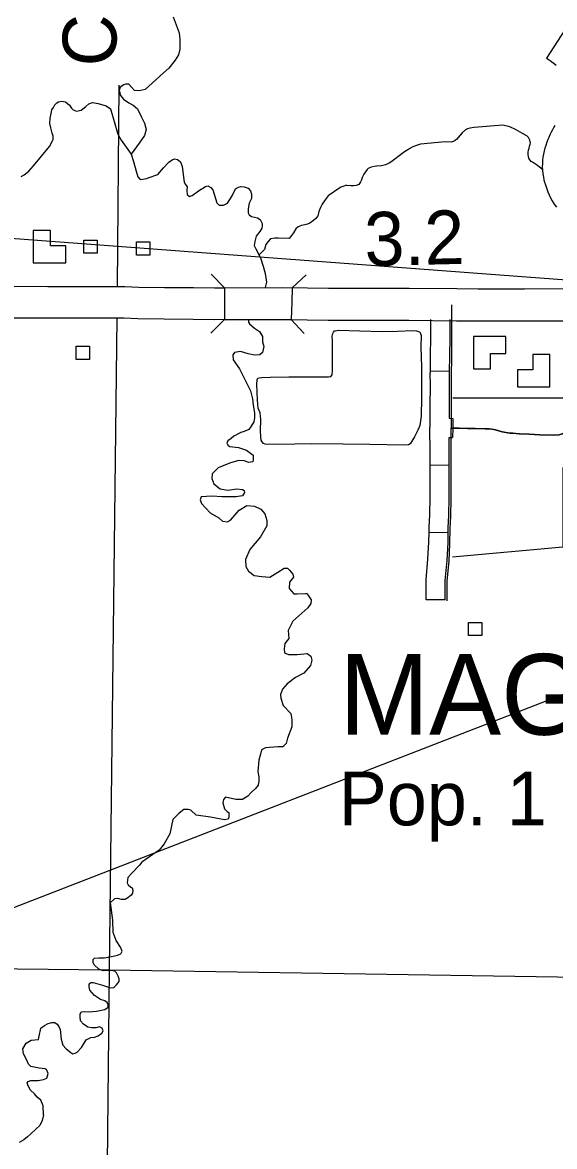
# Model space of a CAD drawing. Extents: x 61396 to 64680, y 55472 to 57605.
# Drawn here: x 62426.4 to 62557, y 55839.3 to 56115 of the extents above; entities that cross this region are included whole.
import ezdxf

# ---------------------------------------------------------------- set-up
doc = ezdxf.new("R2010")
doc.units = 0
for name, color, linetype in [('15', 7, 'Continuous'), ('22', 7, 'Continuous'), ('32', 7, 'Continuous'), ('34', 7, 'Continuous'), ('35', 7, 'Continuous'), ('37', 7, 'Continuous'), ('48', 7, 'Continuous'), ('5', 7, 'Continuous'), ('56', 7, 'Continuous'), ('58', 7, 'Continuous'), ('6', 7, 'Continuous'), ('Default', 7, 'Continuous')]:
    doc.layers.add(name, color=color, linetype=linetype)

msp = doc.modelspace()

# ---------------------------------------------------------------- linework, layer by layer
at = {"layer": '15'}
for points in [[(62424.38, 56050.34), (62432.67, 56050.29), (62439.78, 56050.29), (62447.11, 56050.29), (62451.57, 56050.29), (62454.96, 56050.13), (62461.25, 56050.03), (62468.36, 56049.98), (62473.53, 56049.93), (62476, 56049.94), (62475.99, 56046.21), (62475.98, 56042.13)], [(62476, 56049.94), (62490.28, 56049.98), (62492.59, 56049.94)], [(62492.59, 56049.94), (62492.49, 56046.4), (62492.37, 56042.13), (62496.24, 56042.07), (62501.46, 56041.97), (62512.44, 56041.97), (62518.65, 56041.97), (62521.23, 56041.97), (62532.91, 56041.87), (62538.17, 56041.81), (62549.6, 56041.81), (62559.28, 56041.87)], [(62559.33, 56049.68), (62549.58, 56049.63), (62538.21, 56049.63), (62532.98, 56049.68), (62521.26, 56049.78), (62518.65, 56049.78), (62512.44, 56049.78), (62501.54, 56049.78), (62496.38, 56049.88), (62492.59, 56049.94)], [(62475.98, 56042.13), (62473.5, 56042.12), (62468.29, 56042.17), (62461.16, 56042.22), (62454.72, 56042.32), (62451.4, 56042.48), (62447.11, 56042.48), (62439.78, 56042.48), (62432.65, 56042.48), (62424.35, 56042.53)], [(62475.98, 56042.13), (62490.23, 56042.17), (62492.37, 56042.13)]]:
    msp.add_lwpolyline(points, dxfattribs=at)
at = {"layer": '22'}
for points in [[(62560.42, 56114.61), (62555.01, 56106.25), (62555.4, 56106.02), (62555.86, 56105.72), (62556.3, 56105.41), (62556.88, 56104.95), (62557.34, 56104.55)], [(62557.02, 56089.74), (62556.71, 56089.21), (62556.44, 56088.72), (62556.14, 56088.14), (62555.81, 56087.46), (62555.52, 56086.79), (62555.31, 56086.29), (62555.07, 56085.66), (62554.81, 56084.88), (62554.6, 56084.23), (62554.41, 56083.52), (62554.22, 56082.7), (62554.1, 56081.97), (62554.02, 56081.21), (62553.97, 56080.37), (62553.96, 56079.59), (62554, 56078.83), (62554.09, 56077.93), (62554.23, 56077.08), (62554.37, 56076.44), (62554.52, 56075.87), (62554.7, 56075.23), (62554.95, 56074.44), (62555.31, 56073.48), (62555.62, 56072.77), (62555.97, 56072.04), (62556.37, 56071.32), (62556.87, 56070.5), (62557.4, 56069.75)]]:
    msp.add_lwpolyline(points, dxfattribs=at)
at = {"layer": '32'}
for p, q in [((62526.41, 56029.6), (62531.1, 56029.51)), ((62531.11, 56006.39), (62526.42, 56006.35)), ((62530.87, 55989.84), (62526.18, 55989.91)), ((62530.15, 55973.4), (62525.46, 55973.4))]:
    msp.add_line(p, q, dxfattribs=at)
for points in [[(62531.64, 56045.78), (62531.71, 56042.56), (62531.71, 56040.2), (62531.71, 56037.67), (62531.65, 56032.89), (62531.56, 56028.4), (62531.59, 56026.04), (62531.56, 56020.42), (62531.56, 56016.05), (62531.56, 56015.52)], [(62526.54, 56042.17), (62526.54, 56040.48), (62526.54, 56037.95), (62526.48, 56033.2), (62526.41, 56029.6)], [(62531.23, 56042.13), (62531.23, 56040.48), (62531.23, 56037.93), (62531.17, 56033.12), (62531.1, 56029.51)], [(62526.41, 56029.6), (62526.39, 56028.68), (62526.42, 56026.3), (62526.39, 56020.69), (62526.39, 56016.31), (62526.4, 56015.78)], [(62531.1, 56029.51), (62531.08, 56028.66), (62531.11, 56026.32), (62531.08, 56020.68), (62531.08, 56017.94)], [(62531.08, 56017.94), (62531.97, 56017.9), (62531.97, 56015.51), (62531.96, 56013.21)], [(62526.42, 56006.35), (62526.42, 56006.58), (62526.42, 56009.32), (62526.4, 56015.78)], [(62530.63, 55973.13), (62530.63, 55977.95), (62531.07, 55982.95), (62531.31, 55987.16), (62531.37, 55990.93), (62531.5, 55993.83), (62531.62, 55998.34), (62531.62, 56002.11), (62531.59, 56006.31), (62531.59, 56009.05), (62531.56, 56015.52)], [(62531.56, 56015.52), (62533.52, 56015.49), (62535.58, 56015.4), (62537.5, 56015.43), (62539.96, 56015.34), (62540.92, 56015.31), (62541.59, 56015.28), (62542.46, 56015.08), (62544.09, 56014.62), (62545.97, 56014.27), (62546.76, 56014.24), (62548.32, 56014.15), (62550.76, 56014.04), (62552.01, 56013.92), (62553.37, 56013.83), (62556.77, 56013.75), (62558.13, 56013.86), (62558.8, 56014.09), (62559.55, 56014.61)], [(62531.11, 56006.39), (62531.11, 56006.59), (62531.11, 56009.33), (62531.09, 56013.24)], [(62531.09, 56013.24), (62531.96, 56013.21)], [(62526.18, 55989.91), (62526.21, 55991.27), (62526.33, 55994.18), (62526.45, 55998.64), (62526.45, 56002.37), (62526.42, 56006.35)], [(62530.87, 55989.84), (62530.89, 55991.13), (62531.02, 55994.02), (62531.14, 55998.58), (62531.14, 56002.39), (62531.11, 56006.39)], [(62525.46, 55973.4), (62525.46, 55978.32), (62525.9, 55983.4), (62526.15, 55987.52), (62526.18, 55989.91)], [(62530.15, 55973.4), (62530.15, 55978.12), (62530.58, 55983.06), (62530.83, 55987.34), (62530.87, 55989.84)]]:
    msp.add_lwpolyline(points, dxfattribs=at)
at = {"layer": '34'}
msp.add_lwpolyline([(62561.74, 56014.61), (62558.8, 56014.09), (62558.13, 56013.86), (62556.77, 56013.75), (62553.37, 56013.83), (62552.01, 56013.92), (62550.76, 56014.04), (62548.32, 56014.15), (62546.76, 56014.24), (62545.97, 56014.27), (62544.09, 56014.62), (62542.46, 56015.08), (62541.59, 56015.28), (62540.92, 56015.31), (62539.96, 56015.34), (62537.5, 56015.43), (62535.58, 56015.4), (62533.52, 56015.49), (62531.97, 56015.51)], dxfattribs=at)
at = {"layer": '35'}
for points in [[(62463.37, 56116.42), (62464.12, 56114.43), (62464.87, 56112.54), (62465.01, 56110.88), (62465.02, 56108.53), (62464.69, 56107.11), (62463.92, 56105.79), (62462.32, 56103.8), (62460.94, 56102.62), (62456.54, 56098.59), (62455.04, 56098.29), (62453.89, 56098.39), (62453.18, 56099.14), (62452.48, 56099.9), (62451.73, 56099.9), (62451.28, 56099.75), (62450.43, 56099.19), (62450.18, 56098.34), (62450.48, 56097.09), (62451.18, 56096.19), (62452.48, 56095.34), (62453.58, 56094.78), (62454.64, 56093.83), (62455.64, 56091.83), (62456.39, 56090.37), (62456.79, 56088.77), (62456.34, 56087.32), (62455.09, 56085.41), (62453.08, 56082.7)], [(62426.11, 56077.28), (62426.82, 56077.62), (62428.01, 56078.54), (62429.1, 56079.83), (62433.09, 56084.6), (62433.8, 56086), (62433.98, 56086.29), (62433.98, 56087.14), (62433.74, 56087.92), (62433.35, 56089.19), (62433.17, 56090.22), (62433.25, 56091.54), (62433.47, 56092.68), (62433.63, 56093.59), (62434.02, 56094.2), (62434.4, 56094.81), (62434.83, 56095.33), (62435.26, 56095.59), (62436, 56095.71), (62436.95, 56095.55), (62437.94, 56094.77), (62438.47, 56094.03), (62438.83, 56093.6), (62439.68, 56093.28), (62440.8, 56093.54), (62442, 56094.39), (62442.67, 56095.04), (62443.63, 56095.39), (62444.98, 56095.18), (62446.94, 56094.55), (62448, 56093.83), (62449.83, 56087.67), (62450.63, 56086.16), (62452.28, 56083.86), (62453.08, 56082.7), (62453.63, 56080.9), (62454.34, 56078.6), (62454.69, 56077.19), (62455.29, 56076.54), (62456.94, 56076.79), (62457.3, 56076.91)], [(62554.04, 56078.89), (62553.97, 56078.95), (62553.3, 56079.58), (62552.81, 56079.98), (62552.08, 56080.46), (62551.51, 56080.78), (62551.22, 56080.96), (62550.89, 56081.33), (62550.63, 56081.76), (62550.48, 56082.54), (62550.52, 56083.23), (62550.57, 56083.73), (62550.74, 56084.18), (62550.79, 56084.68), (62550.96, 56085.22), (62551.05, 56085.51), (62551.01, 56085.79), (62550.93, 56086.16), (62550.6, 56086.81), (62550.15, 56087.2), (62549.1, 56087.77), (62547.41, 56088.78), (62546.01, 56089.43), (62544.24, 56089.87), (62537.28, 56089.27), (62536.19, 56089.08), (62535.6, 56088.94), (62535.1, 56088.7), (62534.28, 56087.98), (62533.79, 56087.4), (62533.28, 56086.79), (62533.01, 56086.38), (62532.58, 56086.05), (62532.12, 56085.84), (62531.62, 56085.7), (62530.15, 56085.78), (62524.06, 56085.21), (62523.1, 56084.83), (62522.23, 56084.52), (62521.46, 56084.12), (62520.94, 56083.82), (62520.14, 56083.3), (62518.82, 56082.34), (62517.81, 56081.5), (62517.01, 56080.97), (62516.4, 56080.54), (62515.51, 56080.1), (62514.48, 56079.88), (62513.32, 56079.75), (62512.67, 56079.67), (62511.95, 56079.52), (62511.27, 56079.25), (62510.97, 56078.96), (62510.55, 56078.38)], [(62457.3, 56076.91), (62459.62, 56077.75), (62460.99, 56079.37), (62462.36, 56080.8), (62463.11, 56081.36), (62463.74, 56081.55), (62464.42, 56081.43), (62465.23, 56080.86), (62465.61, 56079.68), (62466.11, 56075.87), (62466.42, 56075.25), (62466.79, 56074.69), (62466.73, 56073.82), (62466.79, 56072.82), (62467.42, 56072.32), (62468.04, 56072.57), (62469.6, 56073.75), (62471.35, 56074.81), (62471.91, 56074.94), (62472.66, 56074.56), (62473.09, 56073.94), (62474.09, 56070.82), (62474.65, 56070.2), (62475.78, 56070.2), (62476.71, 56070.7), (62477.9, 56072.51), (62478.71, 56074.19), (62479.39, 56074.63), (62480.02, 56074.81), (62480.83, 56074.75), (62481.76, 56074.38), (62482.39, 56073.75), (62482.58, 56072.94), (62482.58, 56071.88), (62482.08, 56070.7), (62481.76, 56069.32), (62481.83, 56068.33), (62482.01, 56067.83), (62482.64, 56067.45), (62484.07, 56067.08), (62484.7, 56066.7), (62485.26, 56065.71), (62485.2, 56065.08), (62485.13, 56064.58), (62484.63, 56063.77), (62483.76, 56062.59), (62483.45, 56061.28), (62483.26, 56060.34), (62483.64, 56059.53), (62484.82, 56057.29), (62485.44, 56055.23), (62485.94, 56053.48), (62486.26, 56051.3), (62485.93, 56049.98)], [(62510.55, 56078.38), (62510.16, 56077.8), (62509.74, 56077.03), (62509.6, 56076.46), (62509.37, 56075.95), (62509.1, 56075.51), (62508.95, 56075.25), (62508.27, 56075.04), (62507.71, 56074.96), (62506.99, 56074.97), (62506.01, 56075.06), (62505.67, 56075.08), (62505.24, 56074.88), (62504.28, 56074.54), (62504.28, 56074.47), (62501.43, 56072.5), (62500.67, 56071.5), (62499.98, 56070.45), (62499.51, 56069.65), (62499.13, 56068.63), (62499.08, 56068.28), (62498.88, 56067.62), (62498.4, 56066.97), (62497.82, 56066.42), (62496.93, 56065.77), (62496.37, 56065.59), (62495.72, 56065.41), (62494.85, 56065.23), (62494.05, 56064.92), (62493.5, 56064.43), (62492.93, 56063.44), (62492.42, 56062.74), (62491.85, 56062.03), (62489.12, 56062.11), (62488.33, 56062.11), (62487.27, 56061.95), (62486.69, 56061.31), (62486.16, 56060.57), (62485.79, 56059.3), (62484.41, 56057.98)], [(62481.85, 56042.14), (62481.89, 56041.51), (62482.14, 56041.13), (62483.39, 56040.07), (62484.57, 56039.26), (62485.32, 56038.01), (62485.32, 56036.7), (62485.63, 56035.58), (62485.32, 56034.08), (62484.63, 56033.46), (62483.32, 56033.4), (62481.83, 56033.71), (62479.89, 56034.33), (62478.46, 56034.08), (62478.02, 56033.52), (62478.15, 56032.27), (62479.64, 56030.09), (62482.33, 56024.66), (62482.89, 56022.73), (62483.01, 56021.17), (62483.39, 56019.24), (62483.39, 56018.05), (62483.2, 56017.05), (62482.51, 56015.99), (62481.95, 56015.18), (62480.83, 56014.68), (62479.99, 56014.44)], [(62479.99, 56014.44), (62478.24, 56013.57), (62477.62, 56012.94), (62476.82, 56012.41), (62476.55, 56011.79), (62476.91, 56011.26), (62477.26, 56010.99), (62479.39, 56010.72), (62481.35, 56010.1), (62483.04, 56008.86), (62483.04, 56007.79), (62482.95, 56007.26), (62481.97, 56007.08), (62480.81, 56007.52), (62479.48, 56007.61), (62477.44, 56006.99), (62474.42, 56005.75), (62473, 56004.33), (62472.91, 56003.17), (62473.35, 56001.84), (62474.95, 56000.6), (62476.82, 56000.33), (62479.04, 56000.6), (62480.37, 56000.42), (62480.81, 56000.24), (62480.9, 55999.71), (62480.37, 55998.91), (62478.86, 55998.64), (62475.4, 55998.64), (62472.91, 55998.82), (62470.24, 55998.64), (62469.98, 55997.93), (62470.33, 55997.04), (62472.46, 55994.73), (62474.6, 55993.49), (62475.48, 55992.69), (62476.73, 55992.51), (62477.44, 55992.96), (62479.57, 55995.35), (62481.44, 55996.51), (62483.39, 55996.33), (62484.9, 55995.62), (62485.88, 55994.47), (62486.41, 55992.87), (62486.41, 55991.53), (62484.81, 55988.87), (62482.24, 55985.76), (62481.17, 55983.27), (62481.26, 55981.58), (62481.88, 55980.43), (62483.3, 55979.36), (62485.17, 55979.1), (62487.12, 55978.92), (62489.08, 55980.16), (62490.59, 55981.14), (62491.48, 55981.14), (62491.92, 55980.7), (62492.72, 55979.72), (62492.9, 55978.92), (62491.92, 55977.68), (62491.83, 55976.17), (62492.99, 55974.83), (62493.79, 55974.83), (62495.83, 55974.92), (62496.27, 55974.92), (62496.63, 55974.39), (62497.25, 55973.41), (62497.16, 55972.52), (62496.45, 55971.46), (62492.72, 55968.17), (62491.57, 55965.86), (62491.74, 55963.91), (62490.77, 55962.66), (62490.59, 55961.33), (62490.68, 55960.35), (62491.65, 55960), (62493.79, 55960), (62496.27, 55960.18), (62497.16, 55959.55), (62497.43, 55958.58), (62497.07, 55957.24), (62495.47, 55955.38), (62493.43, 55954.31), (62491.39, 55952.8), (62490.23, 55951.47), (62489.7, 55950.14), (62489.79, 55949.25), (62490.41, 55947.47), (62492.28, 55945.52), (62492.54, 55944.01), (62492.54, 55942.23), (62491.48, 55939.48), (62491.12, 55938.15), (62490.34, 55937.33), (62489.08, 55937.28), (62486.07, 55937.11), (62485.1, 55936.59), (62484.82, 55935.51), (62484.42, 55934.03), (62484.19, 55931.25), (62484.42, 55929.94)], [(62484.42, 55929.94), (62484.42, 55928.97), (62484.25, 55927.95), (62483.62, 55927.09), (62482.43, 55926.01), (62481.74, 55925.22), (62480.38, 55924.36), (62478.79, 55924.36), (62476.23, 55924.93), (62475.77, 55924.36), (62475.6, 55923.57), (62476, 55922.14), (62476.68, 55921.46), (62477.02, 55921.18), (62477.08, 55920.55), (62477.02, 55920.1), (62476.85, 55919.58), (62476, 55919.41), (62472.53, 55920.1), (62469.06, 55920.55), (62467.75, 55921.8), (62467.06, 55921.97), (62465.98, 55921.92), (62464.9, 55921.06), (62463.31, 55919.47), (62462.57, 55916), (62461.2, 55913.55), (62459.95, 55911.96), (62458.42, 55910.88), (62455.68, 55909), (62455.12, 55908.26), (62453.35, 55906.44), (62452.27, 55905.25), (62452.1, 55903.99), (62452.33, 55903.43), (62453.01, 55902.86), (62453.35, 55902.69), (62453.52, 55902.17), (62453.41, 55901.43), (62453.07, 55900.92), (62452.27, 55900.3), (62451.59, 55899.84), (62450.68, 55899.9), (62449.82, 55900.07), (62449.03, 55900.01), (62448.74, 55899.78)], [(62431.6, 55847.06), (62431.47, 55849.25), (62430.95, 55850.6), (62430.05, 55851.37), (62429.34, 55852.14), (62428.38, 55853.11), (62427.8, 55854.13), (62427.61, 55854.91), (62427.8, 55855.23), (62428.44, 55855.42), (62430.31, 55855.48), (62431.6, 55855.68), (62432.43, 55856.06), (62432.75, 55857.16), (62432.3, 55858.12), (62431.98, 55858.31), (62430.5, 55858.51), (62428.44, 55858.89), (62427.93, 55859.47), (62427.48, 55860.43), (62426.71, 55861.98), (62426.52, 55863.2), (62427.35, 55864.61), (62428.57, 55865.32), (62430.37, 55865.51), (62430.5, 55866.35), (62430.95, 55868.28), (62431.85, 55868.98), (62432.75, 55869.43), (62433.65, 55869.69), (62434.36, 55869.69), (62434.94, 55869.3), (62435.32, 55868.66), (62435.71, 55867.95), (62435.9, 55865.58), (62436.29, 55864.16), (62437.12, 55863.2), (62438.28, 55862.3), (62438.8, 55861.98), (62439.37, 55862.17), (62439.82, 55862.43), (62440.92, 55863.52), (62442.07, 55865.45), (62443.23, 55866.03), (62444.13, 55866.09), (62445.03, 55866.41), (62445.93, 55867.05), (62446.25, 55867.63), (62446, 55868.28), (62445.35, 55868.6), (62444.45, 55868.4), (62443.36, 55868.4), (62442.46, 55868.53), (62441.37, 55869.24), (62440.66, 55870.08), (62440.6, 55871.17), (62440.6, 55871.75), (62440.85, 55872.33), (62441.62, 55872.39), (62442.78, 55872.33), (62444.58, 55872.45), (62446.64, 55872.9), (62447.41, 55873.48), (62447.41, 55874), (62447.22, 55874.58), (62446.64, 55874.96), (62445.55, 55875.35), (62444.13, 55876.31), (62442.97, 55877.6), (62442.78, 55878.43), (62442.78, 55879.2), (62443.23, 55879.53), (62443.81, 55879.53), (62446.06, 55878.88), (62448.05, 55878.18), (62448.83, 55878.3), (62449.47, 55878.95), (62450.18, 55879.78), (62450.18, 55880.36), (62449.92, 55881.07), (62449.53, 55881.84), (62449.08, 55882.29), (62448.05, 55882.48), (62446.19, 55882.35), (62445.16, 55882.8), (62444, 55883.83), (62443.81, 55884.41), (62443.75, 55885.12), (62444.13, 55885.5), (62445.16, 55885.57), (62446.51, 55885.57), (62448.7, 55885.95), (62449.73, 55886.21), (62450.56, 55886.53), (62450.88, 55887.18), (62450.5, 55888.2), (62449.4, 55889.81), (62448.7, 55891.8), (62448.63, 55894.83), (62448.06, 55899.16), (62448.74, 55899.78)], [(62431.6, 55847.06), (62431.27, 55845.67), (62430.69, 55844.43), (62429.81, 55843.63), (62428.43, 55842.31), (62427.62, 55841.66), (62426.75, 55840.93), (62425.58, 55840.2)]]:
    msp.add_lwpolyline(points, dxfattribs=at)
msp.add_lwpolyline([(62503.24, 56039.42), (62503.91, 56039.54), (62509.16, 56039.42), (62514.66, 56039.25), (62518.45, 56039.29), (62522.15, 56039.46), (62523.07, 56039.37), (62523.57, 56039.25), (62523.9, 56039.08), (62524.11, 56038.75), (62524.24, 56038.25), (62524.19, 56035.46), (62524.28, 56030.5), (62524.28, 56022.97), (62524.24, 56018.43), (62523.94, 56016.18), (62523.49, 56015.18), (62522.57, 56013.35), (62521.57, 56011.68), (62521.15, 56011.43), (62520.07, 56011.35), (62511.62, 56011.47), (62505.12, 56011.6), (62497.41, 56011.68), (62489.04, 56011.51), (62486, 56011.56), (62485.54, 56011.72), (62485.21, 56012.14), (62485, 56012.55), (62484.92, 56013.26), (62484.79, 56014.93), (62484.92, 56017.64), (62484.71, 56019.26), (62484.21, 56020.43), (62484.08, 56022.38), (62483.92, 56026.26), (62484, 56027.38), (62484.17, 56027.76), (62484.5, 56027.88), (62485.17, 56027.92), (62487.17, 56028.01), (62491.75, 56028.09), (62497.83, 56028.09), (62501.54, 56028.13), (62502.08, 56028.17), (62502.37, 56028.59), (62502.45, 56029.55), (62502.49, 56036.96), (62502.41, 56038.04), (62502.54, 56038.71), (62502.7, 56039.08), (62502.99, 56039.37)], close=True, dxfattribs=at)
at = {"layer": '37'}
for points in [[(62472.72, 56053.27), (62476, 56049.94)], [(62492.59, 56049.94), (62496.06, 56053.14)], [(62475.98, 56042.13), (62472.65, 56038.83)], [(62495.57, 56038.71), (62492.37, 56042.13)]]:
    msp.add_lwpolyline(points, dxfattribs=at)
at = {"layer": '5'}
for points in [[(62450.04, 56099.68), (62449.67, 56050.29)], [(62449.59, 56042.48), (62447.66, 55882.61)], [(62282.84, 55884.38), (62447.66, 55882.61)], [(62447.66, 55882.61), (62446.06, 55723.76)], [(62447.66, 55882.61), (62615.36, 55879.98)]]:
    msp.add_lwpolyline(points, dxfattribs=at)
at = {"layer": '56'}
for points in [[(62441.45, 56058.4), (62441.45, 56061.65), (62444.72, 56061.65), (62444.72, 56058.4)], [(62454.41, 56057.95), (62454.41, 56061.2), (62457.67, 56061.2), (62457.67, 56057.95)], [(62439.63, 56032.36), (62439.63, 56035.61), (62442.89, 56035.61), (62442.89, 56032.36)], [(62535.84, 55964.6), (62535.84, 55967.85), (62539.11, 55967.85), (62539.11, 55964.6)]]:
    msp.add_lwpolyline(points, close=True, dxfattribs=at)
at = {"layer": '58'}
for points in [[(62429.09, 56056.07), (62437.03, 56056.07), (62437.03, 56060.26), (62433.28, 56060.26), (62433.28, 56064.01), (62429.09, 56064.01)], [(62537.09, 56037.98), (62537.09, 56030.04), (62541.28, 56030.04), (62541.28, 56033.8), (62545.03, 56033.8), (62545.03, 56037.98)], [(62555.79, 56025.66), (62555.79, 56033.6), (62551.6, 56033.6), (62551.6, 56029.84), (62547.85, 56029.84), (62547.85, 56025.66)]]:
    msp.add_lwpolyline(points, close=True, dxfattribs=at)
at = {"layer": '6'}
msp.add_line((62531.98, 56022.96), (62559.15, 56022.91), dxfattribs=at)
msp.add_lwpolyline([(62559.03, 56005.88), (62559.03, 55995.14), (62559.03, 55986.32), (62531.9, 55983.88)], dxfattribs=at)
at = {"layer": 'Default'}
for p, q in [((62028.43, 56091.83), (62651.44, 56045.01)), ((62046.64, 55751.5), (62762.7, 56029.16))]:
    msp.add_line(p, q, dxfattribs=at)

# ---------------------------------------------------------------- texts
at = {"layer": '35'}
msp.add_text('Creek', height=13.2, rotation=89.061, dxfattribs=at).set_placement((62449.38, 56104.19))
at = {"layer": '48'}
msp.add_text('3.2', height=13.2, rotation=1.3307, dxfattribs=at).set_placement((62510.44, 56055.26))
at = {"layer": '6'}
for s, height, p in [('MAGNOLIA', 19.8, (62504.14, 55940.29)), ('Pop. 1 1,577', 13.2, (62504.03, 55918.06))]:
    msp.add_text(s, height=height, dxfattribs=at).set_placement(p)

doc.saveas('drawing.dxf')
